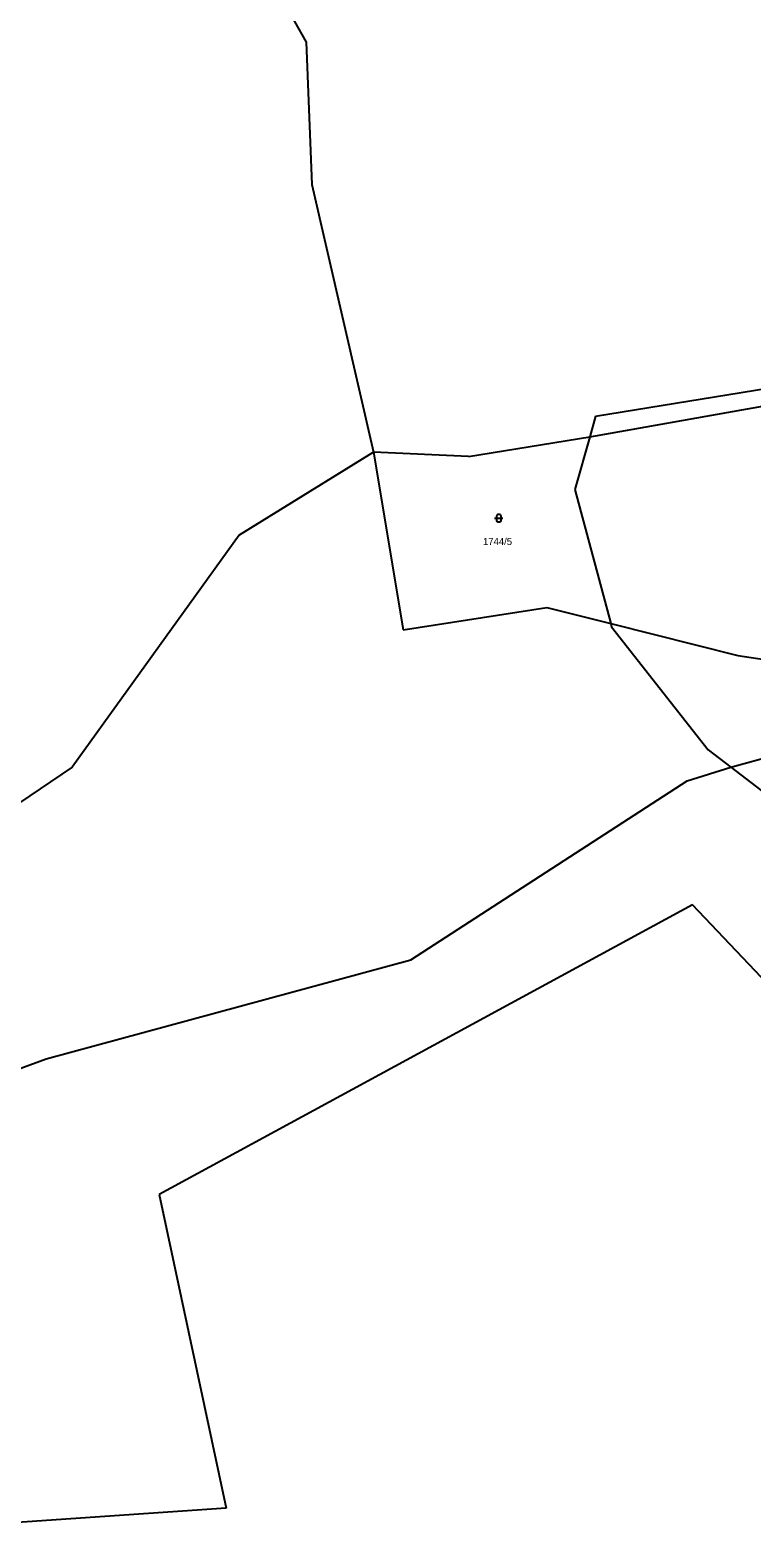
# Model space of a CAD drawing. Extents: x -747792 to -745414, y -1093712 to -1091463.
# Drawn here: x -746752.4 to -746665.7, y -1091925.9 to -1091744.9 of the extents above; entities that cross this region are included whole.
import ezdxf

# ---------------------------------------------------------------- set-up
doc = ezdxf.new("R2010")
doc.units = 0
for name, color, linetype in [('Pracovní_bod JDTM STC_VC', 7, 'Continuous'), ('Pracovní_bod JDTM STC_VC - číslo', 7, 'Continuous'), ('Pracovní_bod NN - výška', 7, 'Continuous')]:
    doc.layers.add(name, color=color, linetype=linetype)

msp = doc.modelspace()

# ---------------------------------------------------------------- linework, layer by layer
at = {"layer": 'Pracovní_bod JDTM STC_VC - číslo'}
msp.add_lwpolyline([(-746696.36, -1091803.25), (-746696.31, -1091803.1), (-746696.19, -1091803.02), (-746696.03, -1091803.02), (-746695.91, -1091803.1), (-746695.85, -1091803.25), (-746695.85, -1091803.75), (-746695.91, -1091803.9), (-746696.03, -1091803.98), (-746696.19, -1091803.98), (-746696.31, -1091803.9), (-746696.36, -1091803.75)], close=True, dxfattribs=at)
msp.add_lwpolyline([(-746696.61, -1091803.5), (-746695.97, -1091803.5), (-746695.61, -1091803.5)], dxfattribs=at)
at = {"layer": 'Pracovní_bod NN - výška'}
for points in [[(-746744.87, -1091700.93), (-746719.23, -1091746.35)], [(-746719.23, -1091746.35), (-746718.54, -1091763.42)], [(-746718.54, -1091763.42), (-746711.15, -1091795.55)], [(-746684.5, -1091791.23), (-746639.94, -1091784.01)], [(-746685.2, -1091793.71), (-746647.35, -1091787)], [(-746684.5, -1091791.23), (-746685.2, -1091793.71)], [(-746699.75, -1091796.08), (-746685.2, -1091793.71)], [(-746685.2, -1091793.71), (-746687, -1091800.06)], [(-746711.15, -1091795.55), (-746727.28, -1091805.53)], [(-746711.15, -1091795.55), (-746707.58, -1091816.9)], [(-746699.75, -1091796.08), (-746711.15, -1091795.55)], [(-746687, -1091800.06), (-746682.68, -1091816.14)], [(-746727.28, -1091805.53), (-746747.33, -1091833.38)], [(-746707.58, -1091816.9), (-746690.34, -1091814.22)], [(-746690.34, -1091814.22), (-746682.68, -1091816.14)], [(-746682.68, -1091816.14), (-746667.42, -1091819.96)], [(-746682.68, -1091816.14), (-746682.58, -1091816.51)], [(-746682.58, -1091816.51), (-746670.97, -1091831.28)], [(-746667.42, -1091819.96), (-746628.73, -1091825.76)], [(-746670.97, -1091831.28), (-746668.26, -1091833.36)], [(-746668.26, -1091833.36), (-746663.04, -1091831.93)], [(-746747.33, -1091833.38), (-746782.02, -1091856.83)], [(-746673.49, -1091834.99), (-746668.26, -1091833.36)], [(-746668.26, -1091833.36), (-746617.36, -1091872.4)], [(-746706.67, -1091856.49), (-746673.49, -1091834.99)], [(-746672.88, -1091849.9), (-746736.88, -1091884.65)], [(-746618.72, -1091906.94), (-746672.88, -1091849.9)], [(-746750.44, -1091868.36), (-746706.67, -1091856.49)], [(-746797.14, -1091885.54), (-746750.44, -1091868.36)], [(-746736.88, -1091884.65), (-746728.82, -1091922.28)], [(-746728.82, -1091922.28), (-746780.71, -1091925.85)]]:
    msp.add_lwpolyline(points, dxfattribs=at)

# ---------------------------------------------------------------- texts
at = {"layer": 'Pracovní_bod JDTM STC_VC'}
msp.add_text('1744/5', height=0.85, dxfattribs=at).set_placement((-746698, -1091806.7))

doc.saveas('drawing.dxf')
